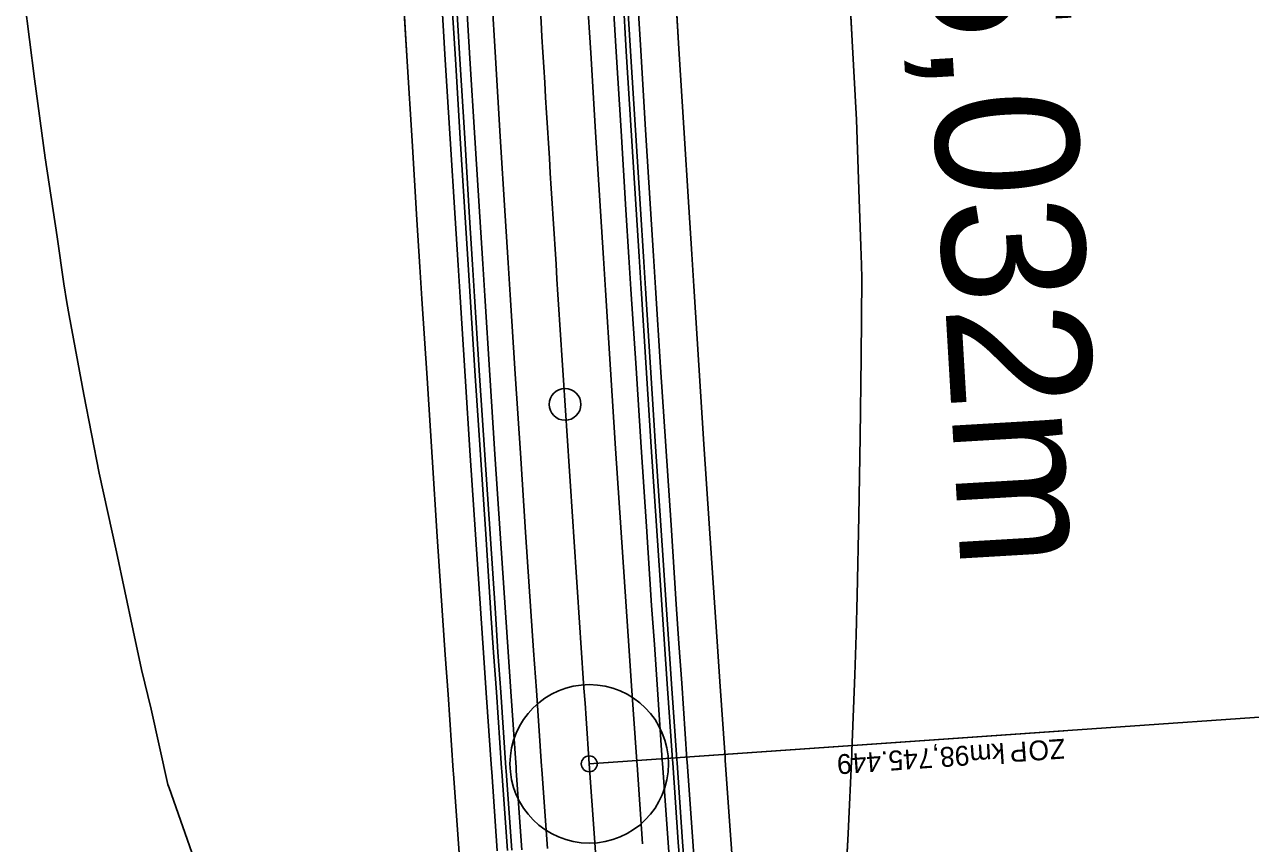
# Model space of a CAD drawing. Extents: x -678487 to -674601, y -1104811 to -1093295.
# Drawn here: x -677521.4 to -677366.8, y -1095550.4 to -1095447.1 of the extents above; entities that cross this region are included whole.
import ezdxf

# ---------------------------------------------------------------- set-up
doc = ezdxf.new("R2010")
doc.units = 0
for name, color, linetype in [('SOxxxxxx_Koleje_hlavní_body_Popis', 7, 'Continuous'), ('SOxxxxxx_Koleje_hlavní_body_Popis10', 7, 'Continuous'), ('SOxxxxxx_Koleje_param další_Popis10', 7, 'Continuous'), ('SOxxxxxx_Osa_bod_P', 7, 'Continuous'), ('SOxxxxxx_Staničení_Popis', 7, 'Continuous'), ('SOxxxxxx_ŽSp_hrana', 7, 'Continuous'), ('SOxxxxxx_ŽSp_odvodnění', 7, 'Continuous'), ('SOxxxxxx_ŽSp_zářez_hrana', 7, 'Continuous'), ('SOxxxxxx_ŽSp_zářez_plocha', 7, 'Continuous')]:
    doc.layers.add(name, color=color, linetype=linetype)

msp = doc.modelspace()

# ---------------------------------------------------------------- linework, layer by layer
at = {"layer": 'SOxxxxxx_Koleje_hlavní_body_Popis'}
for q in [(-677390.37, -1095536.19), (-677450.22, -1095540.36)]:
    msp.add_line((-677450.22, -1095540.36), q, dxfattribs=at)
msp.add_circle((-677450.22, -1095540.36), 1, dxfattribs=at)
at = {"layer": 'SOxxxxxx_Koleje_hlavní_body_Popis10'}
for q in [(-676851.68, -1095498.6), (-677450.22, -1095540.36)]:
    msp.add_line((-677450.22, -1095540.36), q, dxfattribs=at)
msp.add_circle((-677450.22, -1095540.36), 10, dxfattribs=at)
at = {"layer": 'SOxxxxxx_Osa_bod_P'}
msp.add_arc((-668968.6, -1094948.57), 8502.25, 183.991255, 200.113006, dxfattribs=at)
msp.add_open_spline([(-677464.93, -1095295.77), (-677463.8, -1095316.16), (-677461.55, -1095356.94), (-677458.05, -1095418.1), (-677454.35, -1095479.24), (-677451.65, -1095519.99), (-677450.22, -1095540.36)], degree=3, dxfattribs=at)
at = {"layer": 'SOxxxxxx_Staničení_Popis'}
msp.add_line((-677453.27, -1095495.02), (-677453.27, -1095495.02), dxfattribs=at)
msp.add_circle((-677453.27, -1095495.02), 2, dxfattribs=at)
at = {"layer": 'SOxxxxxx_ŽSp_hrana'}
for p, q in [((-677450.65, -1095440.7), (-677450.04, -1095450.69)), ((-677462.66, -1095441.26), (-677462.05, -1095451.25)), ((-677462.05, -1095451.25), (-677461.44, -1095461.23)), ((-677450.04, -1095450.69), (-677449.43, -1095460.67)), ((-677449.43, -1095460.67), (-677448.81, -1095470.65)), ((-677461.44, -1095461.23), (-677460.81, -1095471.21)), ((-677460.81, -1095471.21), (-677460.44, -1095477.15)), ((-677448.81, -1095470.65), (-677448.43, -1095476.58)), ((-677460.44, -1095477.15), (-677460.18, -1095481.19)), ((-677448.43, -1095476.58), (-677448.18, -1095480.62)), ((-677448.18, -1095480.62), (-677447.54, -1095490.6)), ((-677460.18, -1095481.19), (-677459.55, -1095491.17)), ((-677459.55, -1095491.17), (-677458.9, -1095501.15)), ((-677447.54, -1095490.6), (-677446.89, -1095500.58)), ((-677458.9, -1095501.15), (-677458.24, -1095511.13)), ((-677446.89, -1095500.58), (-677446.23, -1095510.55)), ((-677458.24, -1095511.13), (-677457.57, -1095521.11)), ((-677446.23, -1095510.55), (-677445.56, -1095520.53)), ((-677457.57, -1095521.11), (-677457.23, -1095526.05)), ((-677445.56, -1095520.53), (-677445.23, -1095525.47)), ((-677445.23, -1095525.47), (-677444.88, -1095530.5)), ((-677457.23, -1095526.05), (-677456.89, -1095531.09)), ((-677444.88, -1095530.5), (-677444.22, -1095540.07)), ((-677456.89, -1095531.09), (-677456.23, -1095540.66)), ((-677456.23, -1095540.66), (-677456.2, -1095541.06)), ((-677456.2, -1095541.06), (-677455.5, -1095551.04)), ((-677444.22, -1095540.07), (-677444.19, -1095540.47)), ((-677444.19, -1095540.47), (-677443.49, -1095550.44))]:
    msp.add_line(p, q, dxfattribs=at)
at = {"layer": 'SOxxxxxx_ŽSp_odvodnění'}
for p, q in [((-677446.15, -1095440.49), (-677445.55, -1095450.48)), ((-677445.61, -1095440.47), (-677445, -1095450.45)), ((-677467.7, -1095441.5), (-677467.09, -1095451.48)), ((-677467.15, -1095441.47), (-677466.55, -1095451.46)), ((-677467.09, -1095451.48), (-677466.48, -1095461.46)), ((-677466.55, -1095451.46), (-677465.93, -1095461.44)), ((-677445.55, -1095450.48), (-677444.93, -1095460.46)), ((-677445, -1095450.45), (-677444.39, -1095460.43)), ((-677444.93, -1095460.46), (-677444.31, -1095470.43)), ((-677444.39, -1095460.43), (-677443.76, -1095470.41)), ((-677466.48, -1095461.46), (-677465.86, -1095471.45)), ((-677465.93, -1095461.44), (-677465.31, -1095471.42)), ((-677465.86, -1095471.45), (-677465.49, -1095477.38)), ((-677465.31, -1095471.42), (-677464.94, -1095477.36)), ((-677444.31, -1095470.43), (-677443.94, -1095476.37)), ((-677443.76, -1095470.41), (-677443.39, -1095476.34)), ((-677443.94, -1095476.37), (-677443.68, -1095480.41)), ((-677443.39, -1095476.34), (-677443.13, -1095480.39)), ((-677465.49, -1095477.38), (-677465.23, -1095481.43)), ((-677464.94, -1095477.36), (-677464.68, -1095481.4)), ((-677443.68, -1095480.41), (-677443.04, -1095490.39)), ((-677443.13, -1095480.39), (-677442.49, -1095490.36)), ((-677465.23, -1095481.43), (-677464.59, -1095491.41)), ((-677464.68, -1095481.4), (-677464.04, -1095491.38)), ((-677442.49, -1095490.36), (-677441.85, -1095500.34)), ((-677464.59, -1095491.41), (-677463.94, -1095501.39)), ((-677464.04, -1095491.38), (-677463.39, -1095501.36)), ((-677443.04, -1095490.39), (-677442.4, -1095500.36)), ((-677442.4, -1095500.36), (-677441.74, -1095510.34)), ((-677441.85, -1095500.34), (-677441.19, -1095510.31)), ((-677463.94, -1095501.39), (-677463.28, -1095511.37)), ((-677463.39, -1095501.36), (-677462.73, -1095511.35)), ((-677441.74, -1095510.34), (-677441.07, -1095520.31)), ((-677441.19, -1095510.31), (-677440.52, -1095520.29)), ((-677463.28, -1095511.37), (-677462.61, -1095521.35)), ((-677462.73, -1095511.35), (-677462.06, -1095521.33)), ((-677441.07, -1095520.31), (-677440.73, -1095525.26)), ((-677440.52, -1095520.29), (-677440.18, -1095525.23)), ((-677462.61, -1095521.35), (-677462.28, -1095526.3)), ((-677462.06, -1095521.33), (-677461.73, -1095526.27)), ((-677440.73, -1095525.26), (-677440.39, -1095530.28)), ((-677440.18, -1095525.23), (-677439.84, -1095530.26)), ((-677462.28, -1095526.3), (-677461.93, -1095531.33)), ((-677461.73, -1095526.27), (-677461.38, -1095531.3)), ((-677440.39, -1095530.28), (-677439.73, -1095539.85)), ((-677439.84, -1095530.26), (-677439.18, -1095539.82)), ((-677461.93, -1095531.33), (-677461.27, -1095540.9)), ((-677461.38, -1095531.3), (-677460.72, -1095540.88)), ((-677439.73, -1095539.85), (-677439.7, -1095540.25)), ((-677439.18, -1095539.82), (-677439.15, -1095540.23)), ((-677461.27, -1095540.9), (-677461.24, -1095541.31)), ((-677461.24, -1095541.31), (-677460.54, -1095551.29)), ((-677460.72, -1095540.88), (-677460.69, -1095541.28)), ((-677460.69, -1095541.28), (-677459.99, -1095551.26)), ((-677439.7, -1095540.25), (-677439, -1095550.22)), ((-677439.15, -1095540.23), (-677438.45, -1095550.19)), ((-677439, -1095550.22), (-677438.28, -1095560.19)), ((-677438.45, -1095550.19), (-677437.73, -1095560.16))]:
    msp.add_line(p, q, dxfattribs=at)
at = {"layer": 'SOxxxxxx_ŽSp_zářez_hrana'}
for p, q in [((-677417.63, -1095439.16), (-677417.06, -1095449.14)), ((-677447.43, -1095440.55), (-677446.83, -1095450.53)), ((-677444.33, -1095440.41), (-677443.72, -1095450.39)), ((-677439.51, -1095440.18), (-677438.91, -1095450.16)), ((-677473.79, -1095441.78), (-677473.19, -1095451.77)), ((-677468.98, -1095441.56), (-677468.37, -1095451.54)), ((-677465.87, -1095441.41), (-677465.27, -1095451.4)), ((-677521.44, -1095444), (-677520.18, -1095453.96)), ((-677438.91, -1095450.16), (-677438.29, -1095460.14)), ((-677417.06, -1095449.14), (-677416.54, -1095459.13)), ((-677468.37, -1095451.54), (-677467.76, -1095461.52)), ((-677465.27, -1095451.4), (-677464.65, -1095461.38)), ((-677446.83, -1095450.53), (-677446.21, -1095460.52)), ((-677443.72, -1095450.39), (-677443.11, -1095460.37)), ((-677473.19, -1095451.77), (-677472.57, -1095461.75)), ((-677520.18, -1095453.96), (-677518.84, -1095463.91)), ((-677416.54, -1095459.13), (-677416.17, -1095469.11)), ((-677446.21, -1095460.52), (-677445.59, -1095470.49)), ((-677443.11, -1095460.37), (-677442.48, -1095470.35)), ((-677438.29, -1095460.14), (-677437.67, -1095470.12)), ((-677472.57, -1095461.75), (-677471.95, -1095471.73)), ((-677467.76, -1095461.52), (-677467.14, -1095471.51)), ((-677464.65, -1095461.38), (-677464.03, -1095471.36)), ((-677518.84, -1095463.91), (-677517.31, -1095473.86)), ((-677437.67, -1095470.12), (-677437.3, -1095476.06)), ((-677416.17, -1095469.11), (-677415.99, -1095475.06)), ((-677471.95, -1095471.73), (-677471.58, -1095477.67)), ((-677467.14, -1095471.51), (-677466.76, -1095477.45)), ((-677464.03, -1095471.36), (-677463.66, -1095477.3)), ((-677445.59, -1095470.49), (-677445.22, -1095476.43)), ((-677442.48, -1095470.35), (-677442.11, -1095476.28)), ((-677517.31, -1095473.86), (-677516.49, -1095479.79)), ((-677445.22, -1095476.43), (-677444.96, -1095480.47)), ((-677442.11, -1095476.28), (-677441.85, -1095480.33)), ((-677437.3, -1095476.06), (-677437.04, -1095480.1)), ((-677415.99, -1095475.06), (-677415.89, -1095477.43)), ((-677471.58, -1095477.67), (-677471.32, -1095481.72)), ((-677466.76, -1095477.45), (-677466.51, -1095481.49)), ((-677463.66, -1095477.3), (-677463.4, -1095481.34)), ((-677415.89, -1095477.43), (-677415.83, -1095479.1)), ((-677415.83, -1095479.1), (-677415.92, -1095489.1)), ((-677516.49, -1095479.79), (-677516.1, -1095482.15)), ((-677444.96, -1095480.47), (-677444.32, -1095490.45)), ((-677441.85, -1095480.33), (-677441.22, -1095490.3)), ((-677437.04, -1095480.1), (-677436.4, -1095490.07)), ((-677516.1, -1095482.15), (-677515.79, -1095483.81)), ((-677471.32, -1095481.72), (-677470.68, -1095491.7)), ((-677466.51, -1095481.49), (-677465.87, -1095491.47)), ((-677463.4, -1095481.34), (-677462.76, -1095491.32)), ((-677515.79, -1095483.81), (-677513.95, -1095493.75)), ((-677441.22, -1095490.3), (-677440.57, -1095500.28)), ((-677436.4, -1095490.07), (-677435.75, -1095500.05)), ((-677415.92, -1095489.1), (-677416.04, -1095499.11)), ((-677470.68, -1095491.7), (-677470.03, -1095501.68)), ((-677465.87, -1095491.47), (-677465.22, -1095501.45)), ((-677462.76, -1095491.32), (-677462.11, -1095501.3)), ((-677444.32, -1095490.45), (-677443.67, -1095500.43)), ((-677513.95, -1095493.75), (-677512.01, -1095503.68)), ((-677416.04, -1095499.11), (-677416.21, -1095509.12)), ((-677443.67, -1095500.43), (-677443.02, -1095510.4)), ((-677440.57, -1095500.28), (-677439.91, -1095510.25)), ((-677435.75, -1095500.05), (-677435.09, -1095510.02)), ((-677470.03, -1095501.68), (-677469.38, -1095511.66)), ((-677465.22, -1095501.45), (-677464.56, -1095511.43)), ((-677462.11, -1095501.3), (-677461.45, -1095511.28)), ((-677512.01, -1095503.68), (-677509.83, -1095513.6)), ((-677443.02, -1095510.4), (-677442.35, -1095520.37)), ((-677439.91, -1095510.25), (-677439.24, -1095520.22)), ((-677435.09, -1095510.02), (-677434.43, -1095519.99)), ((-677416.21, -1095509.12), (-677416.42, -1095519.12)), ((-677469.38, -1095511.66), (-677468.71, -1095521.65)), ((-677464.56, -1095511.43), (-677463.89, -1095521.41)), ((-677461.45, -1095511.28), (-677460.79, -1095521.26)), ((-677509.83, -1095513.6), (-677507.74, -1095523.53)), ((-677416.42, -1095519.12), (-677416.56, -1095524.08)), ((-677460.79, -1095521.26), (-677460.45, -1095526.21)), ((-677442.35, -1095520.37), (-677442.01, -1095525.32)), ((-677439.24, -1095520.22), (-677438.91, -1095525.17)), ((-677434.43, -1095519.99), (-677434.09, -1095524.93)), ((-677468.71, -1095521.65), (-677468.37, -1095526.59)), ((-677463.89, -1095521.41), (-677463.56, -1095526.36)), ((-677507.74, -1095523.53), (-677506.7, -1095528.45)), ((-677416.56, -1095524.08), (-677416.75, -1095529.13)), ((-677442.01, -1095525.32), (-677441.67, -1095530.35)), ((-677438.91, -1095525.17), (-677438.56, -1095530.19)), ((-677434.09, -1095524.93), (-677433.75, -1095529.96)), ((-677468.37, -1095526.59), (-677468.03, -1095531.63)), ((-677463.56, -1095526.36), (-677463.21, -1095531.39)), ((-677460.45, -1095526.21), (-677460.11, -1095531.24)), ((-677506.7, -1095528.45), (-677505.46, -1095533.45)), ((-677441.67, -1095530.35), (-677441.01, -1095539.91)), ((-677438.56, -1095530.19), (-677437.9, -1095539.76)), ((-677433.75, -1095529.96), (-677433.09, -1095539.52)), ((-677416.75, -1095529.13), (-677417.11, -1095538.74)), ((-677468.03, -1095531.63), (-677467.36, -1095541.2)), ((-677463.21, -1095531.39), (-677462.55, -1095540.97)), ((-677460.11, -1095531.24), (-677459.44, -1095540.81)), ((-677505.46, -1095533.45), (-677503.38, -1095542.97)), ((-677437.9, -1095539.76), (-677437.87, -1095540.16)), ((-677433.09, -1095539.52), (-677433.06, -1095539.93)), ((-677417.12, -1095539.15), (-677417.59, -1095549.16)), ((-677417.11, -1095538.74), (-677417.12, -1095539.15)), ((-677467.36, -1095541.2), (-677467.34, -1095541.61)), ((-677462.55, -1095540.97), (-677462.52, -1095541.37)), ((-677462.52, -1095541.37), (-677461.82, -1095551.35)), ((-677459.44, -1095540.81), (-677459.42, -1095541.22)), ((-677459.42, -1095541.22), (-677458.71, -1095551.2)), ((-677441.01, -1095539.91), (-677440.98, -1095540.32)), ((-677440.98, -1095540.32), (-677440.28, -1095550.28)), ((-677437.87, -1095540.16), (-677437.17, -1095550.13)), ((-677433.06, -1095539.93), (-677432.36, -1095549.89)), ((-677467.34, -1095541.61), (-677466.63, -1095551.59)), ((-677503.38, -1095542.97), (-677503.18, -1095543.37)), ((-677503.18, -1095543.37), (-677499.75, -1095553.23)), ((-677440.28, -1095550.28), (-677439.56, -1095560.25)), ((-677437.17, -1095550.13), (-677436.46, -1095560.1)), ((-677432.36, -1095549.89), (-677431.64, -1095559.86)), ((-677417.59, -1095549.16), (-677418.11, -1095559.18))]:
    msp.add_line(p, q, dxfattribs=at)
at = {"layer": 'SOxxxxxx_ŽSp_zářez_plocha'}
for points in [[(-677477.37, -1095380.69), (-677477.3, -1095381.88), (-677476.73, -1095391.87), (-677476.16, -1095401.85), (-677475.57, -1095411.83), (-677475.16, -1095418.89), (-677474.99, -1095421.82), (-677474.58, -1095428.75), (-677474.39, -1095431.8), (-677473.79, -1095441.78), (-677473.19, -1095451.77), (-677472.57, -1095461.75), (-677471.95, -1095471.73), (-677471.58, -1095477.67), (-677471.32, -1095481.72), (-677470.68, -1095491.7), (-677470.03, -1095501.68), (-677469.38, -1095511.66), (-677468.71, -1095521.65), (-677468.37, -1095526.59), (-677468.03, -1095531.63), (-677467.36, -1095541.2), (-677467.34, -1095541.61), (-677466.63, -1095551.59)], [(-677417.63, -1095439.16), (-677417.06, -1095449.14), (-677416.54, -1095459.13), (-677416.17, -1095469.11), (-677415.99, -1095475.06), (-677415.89, -1095477.43), (-677415.83, -1095479.1), (-677415.92, -1095489.1), (-677416.04, -1095499.11), (-677416.21, -1095509.12), (-677416.42, -1095519.12), (-677416.56, -1095524.08), (-677416.75, -1095529.13), (-677417.11, -1095538.74), (-677417.12, -1095539.15), (-677417.59, -1095549.16), (-677418.11, -1095559.18)], [(-677431.64, -1095559.86), (-677432.36, -1095549.89), (-677433.06, -1095539.93), (-677433.09, -1095539.52), (-677433.75, -1095529.96), (-677434.09, -1095524.93), (-677434.43, -1095519.99), (-677435.09, -1095510.02), (-677435.75, -1095500.05), (-677436.4, -1095490.07), (-677437.04, -1095480.1), (-677437.3, -1095476.06), (-677437.67, -1095470.12), (-677438.29, -1095460.14), (-677438.91, -1095450.16), (-677439.51, -1095440.18)], [(-677499.75, -1095553.23), (-677503.18, -1095543.37), (-677503.38, -1095542.97), (-677505.46, -1095533.45), (-677506.7, -1095528.45), (-677507.74, -1095523.53), (-677509.83, -1095513.6), (-677512.01, -1095503.68), (-677513.95, -1095493.75), (-677515.79, -1095483.81), (-677516.1, -1095482.15), (-677516.49, -1095479.79), (-677517.31, -1095473.86), (-677518.84, -1095463.91), (-677520.18, -1095453.96), (-677521.44, -1095444)]]:
    msp.add_lwpolyline(points, dxfattribs=at)

# ---------------------------------------------------------------- texts
at = {"layer": 'SOxxxxxx_Koleje_hlavní_body_Popis'}
for s, p in [('98,745.449', (-677402.37, -1095538.03)), (' km ', (-677396.97, -1095537.65)), ('P', (-677395.06, -1095537.52)), ('ZO', (-677390.3, -1095537.18))]:
    msp.add_text(s, height=2.5, rotation=183.9913, dxfattribs=at).set_placement(p)
at = {"layer": 'SOxxxxxx_Koleje_param další_Popis10'}
msp.add_text('245,032m', height=18, rotation=273.372, dxfattribs=at).set_placement((-677409.65, -1095409.17))

doc.saveas('drawing.dxf')
